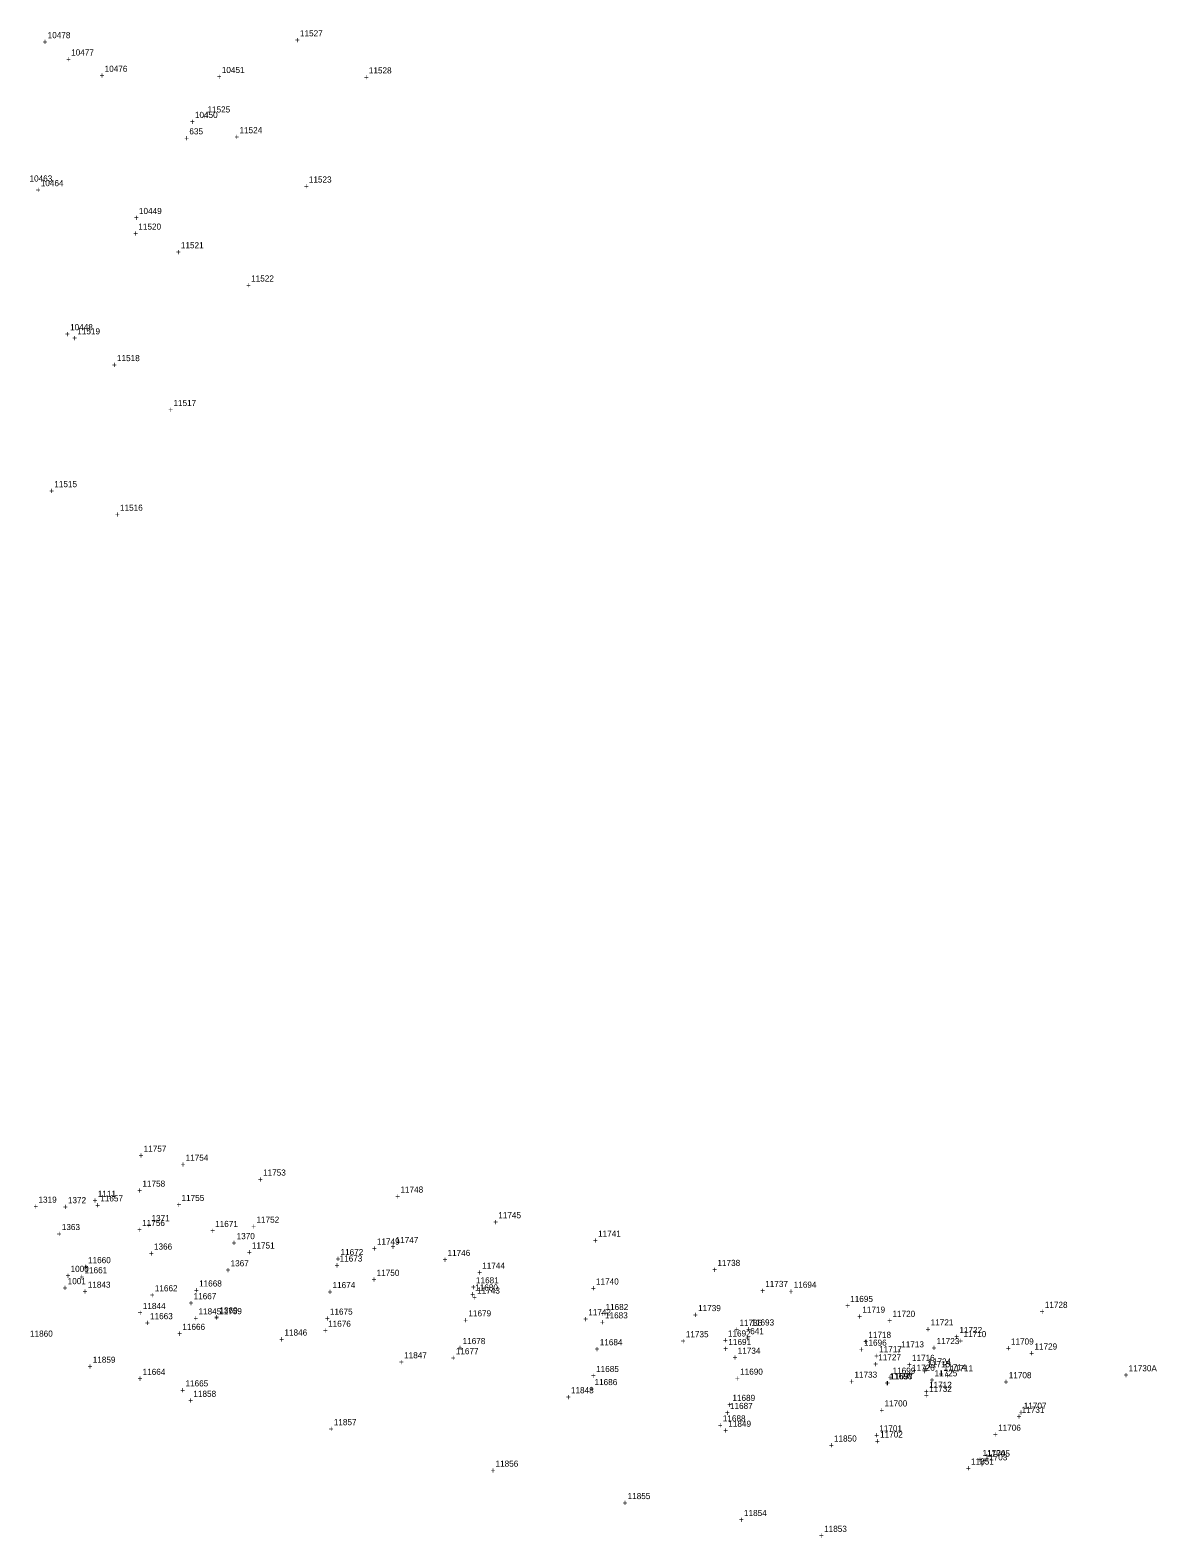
# Model space of a CAD drawing. Extents: x 1160051 to 1162814, y 614604 to 619560.
# Drawn here: x 1161624 to 1162084, y 617094 to 617710 of the extents above; entities that cross this region are included whole.
import ezdxf

# ---------------------------------------------------------------- set-up
doc = ezdxf.new("R2010")
doc.units = 0
for name, color, linetype in [('S_Buildings', 7, 'Continuous'), ('S_Control_Temp_Traverse', 7, 'Continuous'), ('S_Ground_Elevation', 7, 'Continuous'), ('S_Guardrail_Beam', 7, 'Continuous'), ('S_Roadway_Centerline', 7, 'Continuous'), ('S_Roadway_Drive_Gravel', 7, 'Continuous'), ('S_Roadway_Edge_Pavement', 7, 'Continuous'), ('S_Roadway_Edge_Shoulder', 7, 'Continuous'), ('S_Roadway_Entr_Field_Wood', 7, 'Continuous'), ('S_Trees_Decid_Pay', 7, 'Continuous'), ('S_Utilities_Pole_Power', 7, 'Continuous'), ('S_Utilities_UG_Gas_Line', 7, 'Continuous'), ('S_Utilities_UG_Sanitary_MH', 7, 'Continuous')]:
    doc.layers.add(name, color=color, linetype=linetype)

msp = doc.modelspace()

# ---------------------------------------------------------------- texts
at = {"layer": 'S_Buildings'}
for s, p in [('11728', (1162038.33, 617188.04)), ('+', (1162036.27, 617185.29)), ('11729', (1162034.09, 617171.02)), ('+', (1162032.02, 617168.27)), ('+', (1162070.55, 617159.38)), ('11730A', (1162072.61, 617162.13))]:
    msp.add_text(s, height=2.5, dxfattribs=at).set_placement(p)
at = {"layer": 'S_Control_Temp_Traverse'}
for s, p in [('+', (1161686.61, 617664.82)), ('635', (1161688.67, 617667.57)), ('641', (1161917.92, 617177.29)), ('+', (1161915.85, 617174.54))]:
    msp.add_text(s, height=2.5, dxfattribs=at).set_placement(p)
at = {"layer": 'S_Ground_Elevation'}
for s, p in [('10478', (1161630.76, 617706.87)), ('11527', (1161733.88, 617707.63)), ('+', (1161628.7, 617704.12)), ('10477', (1161640.35, 617699.8)), ('+', (1161731.82, 617704.88)), ('+', (1161638.29, 617697.05)), ('10476', (1161654.04, 617693.14)), ('+', (1161651.98, 617690.39)), ('+', (1161759.97, 617689.73)), ('11528', (1161762.04, 617692.48)), ('11525', (1161696.07, 617676.52)), ('+', (1161694.01, 617673.77)), ('+', (1161707.1, 617665.3)), ('11524', (1161709.16, 617668.05)), ('10463', (1161623.34, 617648.3)), ('+', (1161735.45, 617645.14)), ('11523', (1161737.51, 617647.89)), ('+', (1161665.76, 617625.88)), ('11520', (1161667.82, 617628.63)), ('11521', (1161685.2, 617621.03)), ('+', (1161683.14, 617618.28)), ('11522', (1161713.93, 617607.44)), ('+', (1161711.87, 617604.69)), ('+', (1161640.8, 617583.11)), ('11519', (1161642.86, 617585.86)), ('+', (1161657.03, 617572.16)), ('11518', (1161659.09, 617574.91)), ('+', (1161680.11, 617553.8)), ('11517', (1161682.17, 617556.55)), ('+', (1161631.4, 617520.66)), ('11515', (1161633.46, 617523.41)), ('+', (1161658.26, 617511.03)), ('11516', (1161660.32, 617513.78)), ('11757', (1161669.99, 617251.84)), ('+', (1161667.93, 617249.09)), ('+', (1161685.07, 617245.42)), ('11754', (1161687.14, 617248.17)), ('11758', (1161669.49, 617237.56)), ('+', (1161716.73, 617239.34)), ('11753', (1161718.79, 617242.09)), ('+', (1161667.43, 617234.81)), ('11755', (1161685.46, 617231.72)), ('+', (1161772.9, 617232.39)), ('11748', (1161774.96, 617235.14)), ('+', (1161683.4, 617228.97)), ('11745', (1161814.94, 617224.67)), ('+', (1161714.04, 617220.09)), ('11752', (1161716.1, 617222.84)), ('+', (1161812.88, 617221.92)), ('11749', (1161765.32, 617213.9)), ('+', (1161853.68, 617214.39)), ('11741', (1161855.74, 617217.14)), ('+', (1161763.26, 617211.15)), ('+', (1161806.31, 617201.31)), ('11744', (1161808.37, 617204.06)), ('+', (1161902.46, 617202.42)), ('11738', (1161904.52, 617205.17)), ('+', (1161636.87, 617194.98)), ('1001', (1161638.93, 617197.73)), ('11843', (1161647.15, 617196.26)), ('+', (1161852.82, 617194.84)), ('11740', (1161854.88, 617197.59)), ('11737', (1161924.05, 617196.58)), ('+', (1161645.09, 617193.51)), ('11844', (1161669.64, 617187.58)), ('+', (1161921.99, 617193.83)), ('+', (1161667.58, 617184.83)), ('+', (1161690.34, 617182.61)), ('11845', (1161692.4, 617185.36)), ('+', (1161894.55, 617183.96)), ('11739', (1161896.61, 617186.71)), ('+', (1161961.69, 617183.32)), ('11719', (1161963.76, 617186.07)), ('11720', (1161976.06, 617184.36)), ('11860', (1161623.54, 617176.27)), ('11846', (1161727.53, 617176.73)), ('+', (1161911.46, 617177.95)), ('11736', (1161913.52, 617180.7)), ('11718', (1161966.2, 617175.77)), ('+', (1161974, 617181.61)), ('+', (1161989.61, 617178.12)), ('11721', (1161991.67, 617180.87)), ('11722', (1162003.43, 617177.76)), ('+', (1161725.47, 617173.98)), ('+', (1161964.14, 617173.02)), ('11717', (1161970.62, 617169.92)), ('+', (1161992.04, 617170.49)), ('11723', (1161994.1, 617173.24)), ('+', (1162001.37, 617175.01)), ('11859', (1161649.17, 617165.61)), ('+', (1161774.4, 617164.69)), ('11847', (1161776.46, 617167.44)), ('+', (1161968.19, 617163.86)), ('+', (1161968.56, 617167.17)), ('11727', (1161970.25, 617166.61)), ('+', (1161981.96, 617163.61)), ('11716', (1161984.02, 617166.36)), ('11715', (1161990.29, 617163.78)), ('11724', (1161990.74, 617164.88)), ('+', (1161647.11, 617162.86)), ('+', (1161981.99, 617159.58)), ('11726', (1161984.05, 617162.33)), ('+', (1161988.23, 617161.03)), ('+', (1161988.68, 617162.13)), ('+', (1161991.2, 617157.33)), ('11725', (1161993.26, 617160.08)), ('+', (1161994.93, 617159.77)), ('11714', (1161996.99, 617162.52)), ('11858', (1161690.31, 617151.68)), ('11848', (1161844.63, 617153.15)), ('+', (1161688.25, 617148.93)), ('+', (1161842.57, 617150.4)), ('11857', (1161747.71, 617140.1)), ('11849', (1161908.96, 617139.44)), ('+', (1161745.65, 617137.35)), ('+', (1161906.9, 617136.69)), ('11850', (1161952.15, 617133.42)), ('+', (1161950.09, 617130.67)), ('+', (1161811.76, 617120.38)), ('11856', (1161813.82, 617123.13)), ('+', (1162006.12, 617121.28)), ('11851', (1162008.18, 617124.03)), ('11855', (1161867.81, 617109.9)), ('+', (1161865.74, 617107.15)), ('11854', (1161915.38, 617102.98)), ('+', (1161913.32, 617100.23)), ('11853', (1161948.13, 617096.5)), ('+', (1161946.07, 617093.75))]:
    msp.add_text(s, height=2.5, dxfattribs=at).set_placement(p)
at = {"layer": 'S_Guardrail_Beam'}
for s, p in [('+', (1161699.88, 617689.9)), ('10451', (1161701.94, 617692.65)), ('10450', (1161690.93, 617674.29)), ('+', (1161688.86, 617671.54)), ('10464', (1161627.94, 617646.41)), ('+', (1161625.88, 617643.66)), ('+', (1161666, 617632.28)), ('10449', (1161668.06, 617635.03)), ('+', (1161637.85, 617584.79)), ('10448', (1161639.91, 617587.54))]:
    msp.add_text(s, height=2.5, dxfattribs=at).set_placement(p)
at = {"layer": 'S_Roadway_Centerline'}
for s, p in [('1363', (1161636.53, 617219.83)), ('+', (1161634.47, 617217.08)), ('+', (1161672.14, 617209.11)), ('1366', (1161674.2, 617211.86)), ('+', (1161703.47, 617202.27)), ('1367', (1161705.53, 617205.02)), ('11674', (1161747.19, 617196.12)), ('+', (1161745.13, 617193.37)), ('+', (1161800.66, 617181.82)), ('11679', (1161802.72, 617184.57)), ('+', (1161854.35, 617170.01)), ('11684', (1161856.41, 617172.76)), ('+', (1161911.74, 617157.98)), ('11690', (1161913.8, 617160.73)), ('+', (1161970.74, 617145)), ('11700', (1161972.8, 617147.75)), ('+', (1162017.19, 617135.07)), ('11706', (1162019.25, 617137.82))]:
    msp.add_text(s, height=2.5, dxfattribs=at).set_placement(p)
at = {"layer": 'S_Roadway_Drive_Gravel'}
for s, p in [('11694', (1161935.7, 617196.28)), ('+', (1161933.64, 617193.53)), ('11695', (1161958.78, 617190.46)), ('+', (1161956.72, 617187.71)), ('+', (1161916.34, 617178.09)), ('11693', (1161918.4, 617180.84)), ('11710', (1162005.09, 617176.08)), ('+', (1161962.34, 617169.83)), ('11696', (1161964.4, 617172.58)), ('+', (1162003.03, 617173.33)), ('+', (1162022.42, 617170.31)), ('11709', (1162024.49, 617173.06)), ('11697', (1161975.2, 617158.85)), ('+', (1161997.65, 617159.31)), ('11711', (1161999.71, 617162.06)), ('11708', (1162023.59, 617159.3)), ('+', (1161973.14, 617156.1)), ('+', (1161988.96, 617152.59)), ('11712', (1161991.02, 617155.34)), ('+', (1162021.53, 617156.55))]:
    msp.add_text(s, height=2.5, dxfattribs=at).set_placement(p)
at = {"layer": 'S_Roadway_Edge_Pavement'}
for s, p in [('1372', (1161639.02, 617230.82)), ('+', (1161636.96, 617228.07)), ('+', (1161671.14, 617220.7)), ('1371', (1161673.2, 617223.45)), ('+', (1161705.93, 617213.37)), ('1370', (1161708, 617216.12)), ('11660', (1161647.25, 617206.31)), ('11673', (1161750.08, 617206.97)), ('+', (1161645.19, 617203.56)), ('+', (1161748.02, 617204.22)), ('11668', (1161692.64, 617196.78)), ('11680', (1161805.51, 617195.12)), ('+', (1161690.58, 617194.03)), ('+', (1161803.45, 617192.37)), ('+', (1161744.05, 617182.52)), ('11675', (1161746.11, 617185.27)), ('11683', (1161858.56, 617183.75)), ('+', (1161856.5, 617181)), ('+', (1161798.3, 617170.49)), ('11678', (1161800.36, 617173.24)), ('+', (1161906.93, 617170.11)), ('11691', (1161908.99, 617172.86)), ('+', (1161852.87, 617159.08)), ('11685', (1161854.93, 617161.83)), ('11698', (1161974.89, 617158.85)), ('+', (1161972.83, 617156.1)), ('+', (1161908.58, 617147.27)), ('11689', (1161910.64, 617150.02)), ('11707', (1162029.73, 617146.83)), ('+', (1162027.67, 617144.08)), ('+', (1161968.6, 617134.81)), ('11701', (1161970.66, 617137.56)), ('11705', (1162014.77, 617127.29)), ('+', (1162012.71, 617124.54))]:
    msp.add_text(s, height=2.5, dxfattribs=at).set_placement(p)
at = {"layer": 'S_Roadway_Edge_Shoulder'}
for s, p in [('1111', (1161651.23, 617233.4)), ('11657', (1161652.25, 617231.54)), ('+', (1161649.17, 617230.65)), ('+', (1161650.19, 617228.79)), ('11671', (1161699.22, 617221.11)), ('+', (1161697.16, 617218.36)), ('+', (1161748.4, 617206.84)), ('11672', (1161750.46, 617209.59)), ('1000', (1161640.11, 617202.74)), ('11661', (1161645.8, 617202.2)), ('+', (1161638.05, 617199.99)), ('+', (1161643.74, 617199.45)), ('11662', (1161674.55, 617194.81)), ('+', (1161803.77, 617195.31)), ('11681', (1161805.83, 617198.06)), ('+', (1161672.49, 617192.06)), ('+', (1161856.71, 617184.41)), ('11682', (1161858.77, 617187.16)), ('+', (1161743.33, 617177.57)), ('11676', (1161745.39, 617180.32)), ('11692', (1161908.8, 617176.34)), ('11677', (1161797.58, 617169.11)), ('+', (1161906.74, 617173.59)), ('+', (1161795.52, 617166.36)), ('+', (1161974.05, 617158.38)), ('11699', (1161976.11, 617161.13)), ('+', (1161852.21, 617153.73)), ('11686', (1161854.28, 617156.48)), ('11687', (1161909.64, 617146.74)), ('+', (1161907.58, 617143.99)), ('11702', (1161970.99, 617135.07)), ('+', (1161968.93, 617132.32)), ('+', (1162011.65, 617122.99)), ('11703', (1162013.71, 617125.74))]:
    msp.add_text(s, height=2.5, dxfattribs=at).set_placement(p)
at = {"layer": 'S_Roadway_Entr_Field_Wood'}
for s, p in [('+', (1161688.34, 617188.82)), ('11667', (1161690.4, 617191.57)), ('11663', (1161672.59, 617183.42)), ('+', (1161670.53, 617180.67)), ('+', (1161683.75, 617176.3)), ('11666', (1161685.81, 617179.05)), ('+', (1161667.51, 617157.91)), ('11664', (1161669.57, 617160.66)), ('+', (1161685.01, 617153.2)), ('11665', (1161687.08, 617155.95))]:
    msp.add_text(s, height=2.5, dxfattribs=at).set_placement(p)
at = {"layer": 'S_Trees_Decid_Pay'}
for s, p in [('11747', (1161772.99, 617214.54)), ('+', (1161770.92, 617211.79)), ('+', (1161792.14, 617206.51)), ('11746', (1161794.2, 617209.26)), ('11713', (1161979.63, 617171.9)), ('+', (1161977.57, 617169.15))]:
    msp.add_text(s, height=2.5, dxfattribs=at).set_placement(p)
at = {"layer": 'S_Utilities_Pole_Power'}
for s, p in [('+', (1161698.79, 617182.71)), ('+', (1161698.9, 617183.07)), ('11759', (1161700.85, 617185.46)), ('1369', (1161700.96, 617185.82)), ('+', (1161904.66, 617138.89)), ('11688', (1161906.72, 617141.64))]:
    msp.add_text(s, height=2.5, dxfattribs=at).set_placement(p)
at = {"layer": 'S_Utilities_UG_Gas_Line'}
for s, p in [('1319', (1161627, 617231.02)), ('+', (1161624.94, 617228.27)), ('11756', (1161669.38, 617221.5)), ('+', (1161667.32, 617218.75)), ('11751', (1161714.23, 617212.29)), ('+', (1161712.17, 617209.54)), ('11750', (1161765.22, 617201.12)), ('+', (1161763.16, 617198.37)), ('11743', (1161806.31, 617193.89)), ('+', (1161804.25, 617191.14)), ('+', (1161849.65, 617182.27)), ('11742', (1161851.71, 617185.02)), ('11735', (1161891.59, 617176.03)), ('+', (1161889.53, 617173.28)), ('11734', (1161912.8, 617169.27)), ('+', (1161910.74, 617166.52)), ('11733', (1161960.51, 617159.5)), ('+', (1161958.45, 617156.75)), ('11732', (1161991.05, 617153.72)), ('+', (1161988.99, 617150.97)), ('11731', (1162028.89, 617145.15)), ('+', (1162026.83, 617142.4))]:
    msp.add_text(s, height=2.5, dxfattribs=at).set_placement(p)
at = {"layer": 'S_Utilities_UG_Sanitary_MH'}
for s, p in [('11704', (1162012.88, 617127.5)), ('+', (1162010.82, 617124.75))]:
    msp.add_text(s, height=2.5, dxfattribs=at).set_placement(p)

doc.saveas('drawing.dxf')
